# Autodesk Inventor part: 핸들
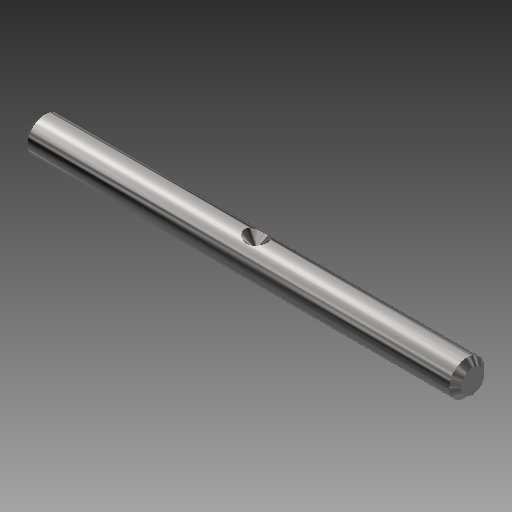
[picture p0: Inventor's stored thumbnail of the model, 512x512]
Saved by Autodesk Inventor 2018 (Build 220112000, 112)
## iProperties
Created: 2019-04
Part Number: 핸들
Material: 스테인리스강
Document SubType Name: Modeling
Designer: mduedu
Density: 1 g/cm^3
Appearance: 반광택
Author: mduedu
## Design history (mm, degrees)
sketch "스케치1"
  geometry: C1 r 3 at (0, 0); 1 further point
  constraints: 1 centre point, 1 coincident
  dimensions: "d0" = 6 diameter of C1
extrude "돌출1" new body sketch "스케치1" stored distance "d1" = 74; taper "d2" = 0 deg
chamfer "모따기1" distance "d3" = 1; stored, may be unused: second distance "d4" = 2, angle "d5" = 45 deg
sketch "스케치2"
  geometry: L1 (-36, 3)-(36, 3) reference; L2 (0, 3)-(0, 1); L3 (0, 1)-(2, 3); L4 (0, 3)-(2, 3); 1 further point
  constraints: 6 end point, 2 perpendicular, 1 midpoint, 1 point on line
  dimensions: "d6" = 4 diameter of L3.end L2; "d8" = 45 deg angle of L3 L2
revolve "회전1" sketch "스케치2" stored, may be unused: angle "d10" = 90 deg
node "작업점1"
  node "작업축1"
  node "작업 평면1"
node "솔리드1"
